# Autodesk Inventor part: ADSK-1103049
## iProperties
Shininess: 50.0
Length Units: 11272
Angle Units: 11279
Time Units: 11290
Mass Units: 11286
Length Display Precision: 4
Angle Display Precision: 2
Compacted: True
Created: 2000-11
Part Number: ADSK-1103049
Document SubType Name: Modeling
Description: WRIST PIN
Mass: 0.78831 g
Surface Area: 1.42511 cm^2
Volume: 0.10055 cm^3
Density: 7.84 g/cm^3
Material: Steel, High Strength Low Alloy
Density: 0.0
Volumn: 0.0
Area: 0.0
PropertySet Name: Model Information
Control State: 0
Master: False
Checked Out: False
Author: Autodesk, Inc.
